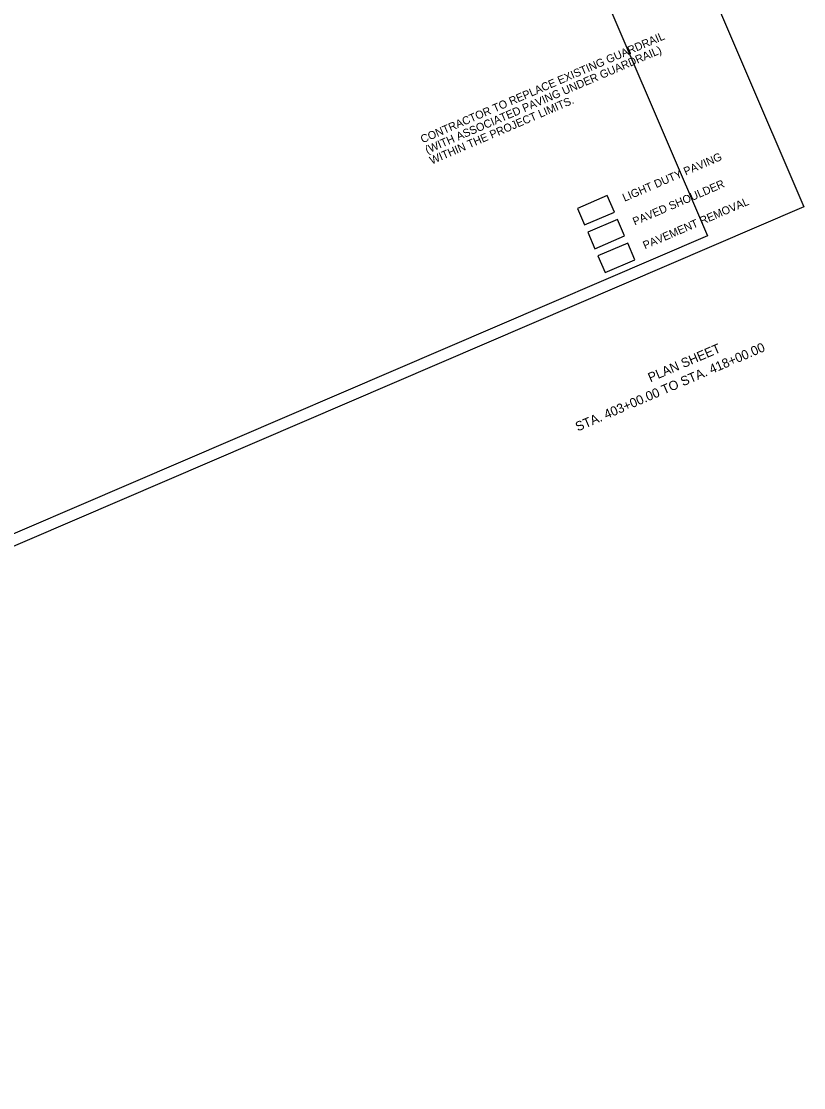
# Model space of a CAD drawing. Extents: x 1618233 to 1620283, y 1101130 to 1102832.
# Drawn here: x 1619562 to 1620150, y 1101154 to 1101953 of the extents above; entities that cross this region are included whole.
import ezdxf

# ---------------------------------------------------------------- set-up
doc = ezdxf.new("R2010")
doc.units = 0
for name, color, linetype in [('RD_EX_DV_TX_Gov', 7, 'Continuous'), ('RD_EX_Fence_Other', 7, 'Continuous'), ('RD_EX_Misc_Golf_Teebox', 7, 'Continuous'), ('RD_EX_RailRoad', 7, 'Continuous')]:
    doc.layers.add(name, color=color, linetype=linetype)

msp = doc.modelspace()

# ---------------------------------------------------------------- linework, layer by layer
at = {"layer": 'RD_EX_Fence_Other'}
msp.add_lwpolyline([(1618233.15, 1102032.67), (1619772.37, 1102693.29), (1620149.61, 1101814.32), (1618610.39, 1101153.71)], close=True, dxfattribs=at)
at = {"layer": 'RD_EX_Misc_Golf_Teebox'}
for points in [[(1619985.21, 1101800.73), (1620007.51, 1101810.3), (1620002.2, 1101822.67), (1619979.9, 1101813.1)], [(1619992.87, 1101782.87), (1620015.17, 1101792.45), (1620009.87, 1101804.81), (1619987.57, 1101795.24)], [(1620000.54, 1101765.02), (1620022.84, 1101774.59), (1620017.53, 1101786.95), (1619995.23, 1101777.38)]]:
    msp.add_lwpolyline(points, close=True, dxfattribs=at)
for points in [[(1619985.21, 1101800.73), (1620007.51, 1101810.3), (1620002.2, 1101822.67), (1619979.9, 1101813.1), (1619985.21, 1101800.73)], [(1619992.87, 1101782.87), (1620015.17, 1101792.45), (1620009.87, 1101804.81), (1619987.57, 1101795.24), (1619992.87, 1101782.87)], [(1620000.54, 1101765.02), (1620022.84, 1101774.59), (1620017.53, 1101786.95), (1619995.23, 1101777.38), (1620000.54, 1101765.02)]]:
    msp.add_lwpolyline(points, dxfattribs=at)
at = {"layer": 'RD_EX_RailRoad'}
msp.add_lwpolyline([(1618327.62, 1102066.11), (1619552.64, 1102591.88), (1619565.97, 1102561.62), (1619719.68, 1102625.9), (1620077.33, 1101792.57), (1618698.92, 1101200.97)], close=True, dxfattribs=at)
msp.add_lwpolyline([(1618327.62, 1102066.11), (1619552.64, 1102591.88), (1619565.97, 1102561.62), (1619719.68, 1102625.9), (1620077.33, 1101792.57), (1618698.92, 1101200.97)], close=True, dxfattribs=at)

# ---------------------------------------------------------------- texts
at = {"layer": 'RD_EX_DV_TX_Gov'}
for s, height, p in [('STA. 403+00.00 TO STA. 418+00.00', 6.9833, (1619980.07, 1101645.73)), ('PLAN SHEET', 6.983, (1620034.57, 1101682.63))]:
    msp.add_text(s, height=height, rotation=23.22835, dxfattribs=at).set_placement(p)
at = {"layer": 'RD_EX_Misc_Golf_Teebox'}
for s, p in [('CONTRACTOR TO REPLACE EXISTING GUARDRAIL', (1619863.63, 1101861.84)), ('(WITH ASSOCIATED PAVING UNDER GUARDRAIL)', (1619867.04, 1101853.89)), ('WITHIN THE PROJECT LIMITS.', (1619870.45, 1101845.95)), ('LIGHT DUTY PAVING', (1620015.17, 1101818.02)), ('PAVED SHOULDER', (1620022.84, 1101800.16)), ('PAVEMENT REMOVAL', (1620030.5, 1101782.31))]:
    msp.add_text(s, height=6, rotation=23.22835, dxfattribs=at).set_placement(p)

doc.saveas('drawing.dxf')
